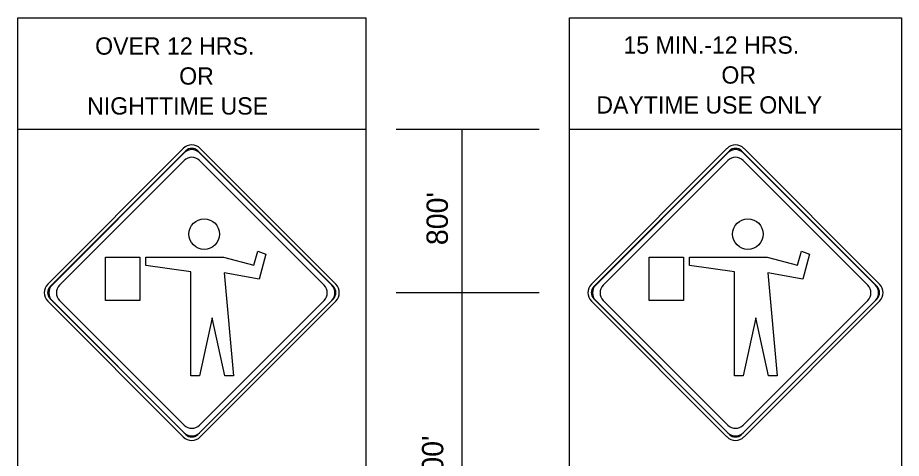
# Model space of a CAD drawing. Extents: x 1531.4 to 1538.6, y 1529.6 to 1539.7.
# Drawn here: x 1535.79 to 1538.277, y 1533.963 to 1535.202 of the extents above; entities that cross this region are included whole.
import ezdxf

# ---------------------------------------------------------------- set-up
doc = ezdxf.new("R2010")
doc.units = 0
for name, color, linetype in [('DETL-DIMS', 7, 'Continuous'), ('DETL-LINE', 7, 'Continuous'), ('DETL-NOTE', 7, 'Continuous')]:
    doc.layers.add(name, color=color, linetype=linetype)

msp = doc.modelspace()

# ---------------------------------------------------------------- linework, layer by layer
at = {"layer": 'DETL-DIMS'}
for p, q in [((1537.2575, 1534.8872), (1536.8556, 1534.8872)), ((1537.0405, 1534.8872), (1537.0405, 1534.4298)), ((1537.2574, 1534.4286), (1536.8555, 1534.4286)), ((1537.2575, 1534.4286), (1536.8556, 1534.4286)), ((1537.0405, 1534.4286), (1537.0405, 1533.5312))]:
    msp.add_line(p, q, dxfattribs=at)
at = {"layer": 'DETL-LINE'}
for p, q in [((1536.77, 1534.8872), (1535.7901, 1534.8872)), ((1538.277, 1534.8872), (1537.3432, 1534.8872)), ((1536.2562, 1534.8343), (1535.8746, 1534.4527)), ((1536.2629, 1534.8274), (1535.8813, 1534.4457)), ((1536.6791, 1534.4457), (1536.2975, 1534.8274)), ((1536.6857, 1534.4527), (1536.3041, 1534.8343)), ((1537.7863, 1534.8343), (1537.4047, 1534.4527)), ((1537.793, 1534.8274), (1537.4114, 1534.4457)), ((1538.2092, 1534.4457), (1537.8276, 1534.8274)), ((1538.2158, 1534.4527), (1537.8342, 1534.8343)), ((1536.2589, 1534.8219), (1535.8867, 1534.4498)), ((1535.9082, 1534.4499), (1536.2588, 1534.8005)), ((1536.3017, 1534.8005), (1536.6524, 1534.4498)), ((1536.6739, 1534.4498), (1536.3018, 1534.8219)), ((1537.789, 1534.8219), (1537.4168, 1534.4498)), ((1537.4383, 1534.4499), (1537.7889, 1534.8005)), ((1537.8318, 1534.8005), (1538.1825, 1534.4498)), ((1538.204, 1534.4498), (1537.8319, 1534.8219)), ((1536.0369, 1534.4067), (1536.0369, 1534.5285)), ((1536.0369, 1534.5285), (1536.1341, 1534.5285)), ((1536.1341, 1534.5285), (1536.1341, 1534.4067)), ((1536.1503, 1534.5046), (1536.1503, 1534.5289)), ((1536.1503, 1534.5289), (1536.3692, 1534.5289)), ((1536.1503, 1534.5289), (1536.3692, 1534.5289)), ((1536.1503, 1534.5046), (1536.1503, 1534.5289)), ((1536.3692, 1534.5289), (1536.4549, 1534.5061)), ((1536.3692, 1534.5289), (1536.4549, 1534.5061)), ((1536.4549, 1534.5061), (1536.4657, 1534.5451)), ((1536.4549, 1534.5061), (1536.4657, 1534.5451)), ((1536.4657, 1534.5451), (1536.4884, 1534.537)), ((1536.4657, 1534.5451), (1536.4884, 1534.537)), ((1536.4884, 1534.537), (1536.4693, 1534.4667)), ((1536.4884, 1534.537), (1536.4693, 1534.4667)), ((1537.567, 1534.4067), (1537.567, 1534.5285)), ((1537.567, 1534.5285), (1537.6642, 1534.5285)), ((1537.6642, 1534.5285), (1537.6642, 1534.4067)), ((1537.6804, 1534.5046), (1537.6804, 1534.5289)), ((1537.6804, 1534.5289), (1537.8993, 1534.5289)), ((1537.6804, 1534.5289), (1537.8993, 1534.5289)), ((1537.6804, 1534.5046), (1537.6804, 1534.5289)), ((1537.8993, 1534.5289), (1537.985, 1534.5061)), ((1537.8993, 1534.5289), (1537.985, 1534.5061)), ((1537.985, 1534.5061), (1537.9958, 1534.5451)), ((1537.985, 1534.5061), (1537.9958, 1534.5451)), ((1537.9958, 1534.5451), (1538.0185, 1534.537)), ((1537.9958, 1534.5451), (1538.0185, 1534.537)), ((1538.0185, 1534.537), (1537.9994, 1534.4667)), ((1538.0185, 1534.537), (1537.9994, 1534.4667)), ((1536.2772, 1534.4869), (1536.1503, 1534.5046)), ((1536.2772, 1534.4869), (1536.1503, 1534.5046)), ((1537.8073, 1534.4869), (1537.6804, 1534.5046)), ((1537.8073, 1534.4869), (1537.6804, 1534.5046)), ((1536.2772, 1534.1951), (1536.2772, 1534.4869)), ((1536.2772, 1534.1951), (1536.2772, 1534.4869)), ((1536.4693, 1534.4667), (1536.3714, 1534.484)), ((1536.3714, 1534.484), (1536.3972, 1534.1951)), ((1536.4693, 1534.4667), (1536.3714, 1534.484)), ((1536.3714, 1534.484), (1536.3972, 1534.1951)), ((1537.8073, 1534.1951), (1537.8073, 1534.4869)), ((1537.8073, 1534.1951), (1537.8073, 1534.4869)), ((1537.9994, 1534.4667), (1537.9015, 1534.484)), ((1537.9015, 1534.484), (1537.9273, 1534.1951)), ((1537.9994, 1534.4667), (1537.9015, 1534.484)), ((1537.9015, 1534.484), (1537.9273, 1534.1951)), ((1535.8746, 1534.4045), (1536.2562, 1534.0233)), ((1535.8813, 1534.4115), (1536.2629, 1534.0299)), ((1535.8867, 1534.4069), (1536.2589, 1534.0348)), ((1536.2589, 1534.0563), (1535.9082, 1534.4069)), ((1536.1341, 1534.4067), (1536.0369, 1534.4067)), ((1536.2975, 1534.0299), (1536.6791, 1534.4115)), ((1536.6524, 1534.4069), (1536.3018, 1534.0563)), ((1536.3018, 1534.0348), (1536.6739, 1534.4069)), ((1536.3041, 1534.0233), (1536.6857, 1534.4045)), ((1537.4047, 1534.4045), (1537.7863, 1534.0233)), ((1537.4114, 1534.4115), (1537.793, 1534.0299)), ((1537.4168, 1534.4069), (1537.789, 1534.0348)), ((1537.789, 1534.0563), (1537.4383, 1534.4069)), ((1537.6642, 1534.4067), (1537.567, 1534.4067)), ((1537.8276, 1534.0299), (1538.2092, 1534.4115)), ((1538.1825, 1534.4069), (1537.8319, 1534.0563)), ((1537.8319, 1534.0348), (1538.204, 1534.4069)), ((1537.8342, 1534.0233), (1538.2158, 1534.4045)), ((1536.3372, 1534.3578), (1536.3015, 1534.1951)), ((1536.3372, 1534.3578), (1536.3015, 1534.1951)), ((1536.3729, 1534.1951), (1536.3372, 1534.3578)), ((1536.3729, 1534.1951), (1536.3372, 1534.3578)), ((1537.8673, 1534.3578), (1537.8316, 1534.1951)), ((1537.8673, 1534.3578), (1537.8316, 1534.1951)), ((1537.903, 1534.1951), (1537.8673, 1534.3578)), ((1537.903, 1534.1951), (1537.8673, 1534.3578)), ((1536.3015, 1534.1951), (1536.2772, 1534.1951)), ((1536.3015, 1534.1951), (1536.2772, 1534.1951)), ((1536.3972, 1534.1951), (1536.3729, 1534.1951)), ((1536.3972, 1534.1951), (1536.3729, 1534.1951)), ((1537.8316, 1534.1951), (1537.8073, 1534.1951)), ((1537.8316, 1534.1951), (1537.8073, 1534.1951)), ((1537.9273, 1534.1951), (1537.903, 1534.1951)), ((1537.9273, 1534.1951), (1537.903, 1534.1951))]:
    msp.add_line(p, q, dxfattribs=at)
for points in [[(1535.7901, 1535.2018), (1536.77, 1535.2018), (1536.77, 1531.3593), (1535.7901, 1531.3593)], [(1537.3432, 1535.2018), (1538.277, 1535.2018), (1538.277, 1532.2226), (1537.3432, 1532.2226)]]:
    msp.add_lwpolyline(points, close=True, dxfattribs=at)
for centre in [(1536.3151, 1534.5933), (1537.8452, 1534.5933)]:
    msp.add_circle(centre, 0.0429, dxfattribs=at)
for centre, radius, start, end in [((1536.28, 1534.8102), 0.0337, 45, 135), ((1536.2803, 1534.8004), 0.0304, 45, 135), ((1536.28, 1534.8102), 0.0242, 45, 135), ((1537.8102, 1534.8102), 0.0337, 45, 135), ((1537.8104, 1534.8004), 0.0304, 45, 135), ((1537.8102, 1534.8102), 0.0242, 45, 135), ((1536.2802, 1534.779), 0.0304, 45, 135), ((1537.8103, 1534.779), 0.0304, 45, 135), ((1535.8985, 1534.4286), 0.0337, 135, 225), ((1536.6616, 1534.4286), 0.0337, 315, 45), ((1537.4286, 1534.4286), 0.0337, 135, 225), ((1538.1917, 1534.4286), 0.0337, 315, 45), ((1535.8985, 1534.4286), 0.0242, 135, 225), ((1535.9082, 1534.4283), 0.0304, 135, 225), ((1535.9296, 1534.4284), 0.0304, 135, 225), ((1536.6309, 1534.4283), 0.0304, 315, 45), ((1536.6524, 1534.4283), 0.0304, 315, 45), ((1536.6616, 1534.4286), 0.0242, 315, 45), ((1537.4286, 1534.4286), 0.0242, 135, 225), ((1537.4383, 1534.4283), 0.0304, 135, 225), ((1537.4597, 1534.4284), 0.0304, 135, 225), ((1538.161, 1534.4283), 0.0304, 315, 45), ((1538.1825, 1534.4283), 0.0304, 315, 45), ((1538.1917, 1534.4286), 0.0242, 315, 45), ((1536.2803, 1534.0777), 0.0304, 225, 315), ((1537.8104, 1534.0777), 0.0304, 225, 315), ((1536.2803, 1534.0562), 0.0304, 225, 315), ((1536.28, 1534.0471), 0.0242, 225, 315), ((1537.8104, 1534.0562), 0.0304, 225, 315), ((1537.8102, 1534.0471), 0.0242, 225, 315), ((1536.28, 1534.0471), 0.0337, 225, 315), ((1537.8102, 1534.0471), 0.0337, 225, 315)]:
    msp.add_arc(centre, radius, start, end, dxfattribs=at)

# ---------------------------------------------------------------- texts
for s, p in [('15 MIN.-12 HRS.', (1537.4949, 1535.1006)), ('OVER 12 HRS.', (1536.0081, 1535.0978)), ('OR', (1536.2446, 1535.0136)), ('OR', (1537.7706, 1535.0164)), ('NIGHTTIME USE', (1535.9856, 1534.9294)), ('DAYTIME USE ONLY', (1537.4186, 1534.9322))]:
    msp.add_text(s, height=0.0486, dxfattribs=at).set_placement(p)
at = {"layer": 'DETL-NOTE'}
for s, p in [("800'", (1537.0008, 1534.5623)), ("700'", (1536.9879, 1533.8778))]:
    msp.add_text(s, height=0.06, rotation=90, dxfattribs=at).set_placement(p)

doc.saveas('drawing.dxf')
